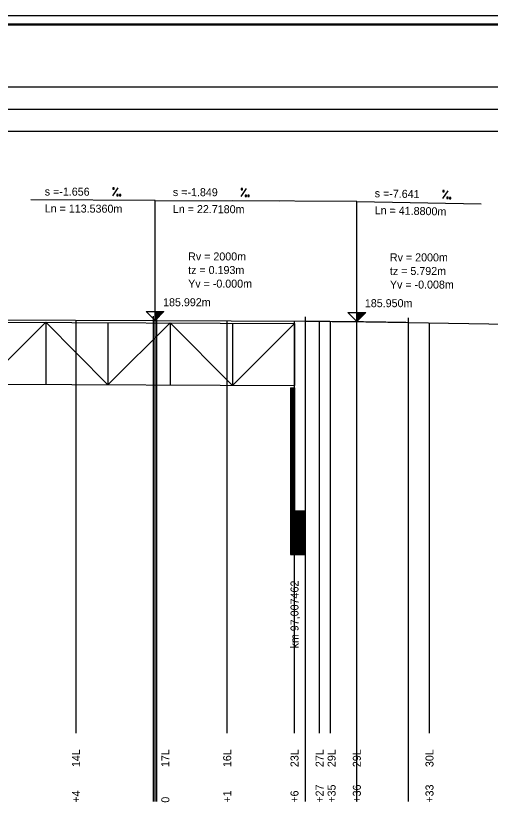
# Model space of a CAD drawing. Extents: x 0 to 10087, y -805 to 297.
# Drawn here: x 1332.1 to 1439, y 120.1 to 297 of the extents above; entities that cross this region are included whole.
import ezdxf

# ---------------------------------------------------------------- set-up
doc = ezdxf.new("R2010")
doc.units = 0
for name, color, linetype in [('CARKY_HODNOT', 7, 'Continuous'), ('NIVELETA_CARA', 7, 'Continuous'), ('NIVELETA_TEXT', 7, 'Continuous'), ('OBJEKTY_TEXT', 7, 'Continuous'), ('OBJEKTY_TVAR', 7, 'Continuous'), ('RAM', 7, 'Continuous'), ('TEXT', 7, 'Continuous')]:
    doc.layers.add(name, color=color, linetype=linetype)

msp = doc.modelspace()

# ---------------------------------------------------------------- linework, layer by layer
at = {"layer": 'CARKY_HODNOT'}
for p, q in [((1345.73, 138.35), (1345.73, 228.53)), ((1363.14, 138.35), (1363.14, 228.46)), ((1363.52, 138.35), (1363.52, 228.46)), ((1363.53, 138.35), (1363.53, 228.46)), ((1363.91, 138.35), (1363.91, 228.46)), ((1379.76, 138.35), (1379.76, 228.38)), ((1394.92, 138.35), (1394.92, 228.31)), ((1397.38, 138.35), (1397.38, 228.3)), ((1400.57, 138.35), (1400.57, 228.29)), ((1403.01, 138.35), (1403.01, 228.27)), ((1408.95, 138.35), (1408.95, 228.21)), ((1408.96, 138.35), (1408.96, 228.21)), ((1420.55, 138.35), (1420.55, 228.03)), ((1425.31, 138.35), (1425.31, 227.94)), ((1345.73, 135.65), (1345.73, 138.35)), ((1363.14, 126.2), (1363.14, 138.35)), ((1363.52, 135.65), (1363.52, 138.35)), ((1363.53, 126.2), (1363.53, 138.35)), ((1363.91, 126.2), (1363.91, 138.35)), ((1379.76, 135.65), (1379.76, 138.35)), ((1394.92, 135.65), (1394.92, 138.35)), ((1397.38, 126.2), (1397.38, 138.35)), ((1400.57, 135.65), (1400.57, 138.35)), ((1403.01, 135.65), (1403.01, 138.35)), ((1408.95, 135.65), (1408.95, 138.35)), ((1408.96, 126.2), (1408.96, 138.35)), ((1420.55, 126.2), (1420.55, 138.35)), ((1425.31, 135.65), (1425.31, 138.35)), ((1363.14, 120.25), (1363.14, 126.2)), ((1363.52, 124.35), (1363.52, 126.2)), ((1363.53, 120.25), (1363.53, 126.2)), ((1363.91, 120.25), (1363.91, 126.2)), ((1397.38, 120.25), (1397.38, 126.2)), ((1408.96, 120.25), (1408.96, 126.2)), ((1420.55, 120.25), (1420.55, 126.2))]:
    msp.add_line(p, q, dxfattribs=at)
at = {"layer": 'NIVELETA_CARA'}
for p, q in [((300, 281), (8321.33, 281)), ((300, 276), (8321.33, 276)), ((300, 271), (8321.33, 271)), ((1363.53, 255.46), (1335.53, 255.58)), ((1363.53, 228.46), (1363.53, 255.46)), ((1363.53, 255.46), (1391.53, 255.33)), ((1408.96, 255.25), (1380.96, 255.38)), ((1408.96, 228.25), (1408.96, 255.25)), ((1408.96, 255.25), (1436.96, 254.72)), ((1363.53, 228.46), (1361.53, 230.46)), ((1361.53, 230.46), (1365.53, 230.46)), ((1363.53, 228.46), (1363.53, 230.46)), ((1365.53, 230.46), (1363.53, 228.46)), ((1363.59, 228.53), (1363.59, 230.46)), ((1363.66, 228.59), (1363.66, 230.46)), ((1363.73, 228.66), (1363.73, 230.46)), ((1363.79, 228.73), (1363.79, 230.46)), ((1363.86, 228.79), (1363.86, 230.46)), ((1363.93, 228.86), (1363.93, 230.46)), ((1363.99, 228.93), (1363.99, 230.46)), ((1364.06, 228.99), (1364.06, 230.46)), ((1364.13, 229.06), (1364.13, 230.46)), ((1364.19, 229.13), (1364.19, 230.46)), ((1364.26, 229.19), (1364.26, 230.46)), ((1364.33, 229.26), (1364.33, 230.46)), ((1364.39, 229.33), (1364.39, 230.46)), ((1364.46, 229.39), (1364.46, 230.46)), ((1364.53, 229.46), (1364.53, 230.46)), ((1364.59, 229.53), (1364.59, 230.46)), ((1364.66, 229.59), (1364.66, 230.46)), ((1364.73, 229.66), (1364.73, 230.46)), ((1364.79, 229.73), (1364.79, 230.46)), ((1364.86, 229.79), (1364.86, 230.46)), ((1364.93, 229.86), (1364.93, 230.46)), ((1364.99, 229.93), (1364.99, 230.46)), ((1365.06, 229.99), (1365.06, 230.46)), ((1365.13, 230.06), (1365.13, 230.46)), ((1365.19, 230.13), (1365.19, 230.46)), ((1365.26, 230.19), (1365.26, 230.46)), ((1365.33, 230.26), (1365.33, 230.46)), ((1365.39, 230.33), (1365.39, 230.46)), ((1365.46, 230.39), (1365.46, 230.46)), ((1408.96, 228.25), (1406.96, 230.25)), ((1406.96, 230.25), (1410.96, 230.25)), ((1408.96, 228.25), (1408.96, 230.25)), ((1410.96, 230.25), (1408.96, 228.25)), ((1409.03, 228.32), (1409.03, 230.25)), ((1409.1, 228.38), (1409.1, 230.25)), ((1409.16, 228.45), (1409.16, 230.25)), ((1409.23, 228.52), (1409.23, 230.25)), ((1409.3, 228.58), (1409.3, 230.25)), ((1409.36, 228.65), (1409.36, 230.25)), ((1409.43, 228.72), (1409.43, 230.25)), ((1409.5, 228.78), (1409.5, 230.25)), ((1409.56, 228.85), (1409.56, 230.25)), ((1409.63, 228.92), (1409.63, 230.25)), ((1409.7, 228.98), (1409.7, 230.25)), ((1409.76, 229.05), (1409.76, 230.25)), ((1409.83, 229.12), (1409.83, 230.25)), ((1409.9, 229.18), (1409.9, 230.25)), ((1409.96, 229.25), (1409.96, 230.25)), ((1410.03, 229.32), (1410.03, 230.25)), ((1410.1, 229.38), (1410.1, 230.25)), ((1410.16, 229.45), (1410.16, 230.25)), ((1410.23, 229.52), (1410.23, 230.25)), ((1410.3, 229.58), (1410.3, 230.25)), ((1410.36, 229.65), (1410.36, 230.25)), ((1410.43, 229.72), (1410.43, 230.25)), ((1410.5, 229.78), (1410.5, 230.25)), ((1410.56, 229.85), (1410.56, 230.25)), ((1410.63, 229.92), (1410.63, 230.25)), ((1410.7, 229.98), (1410.7, 230.25)), ((1410.76, 230.05), (1410.76, 230.25)), ((1410.83, 230.12), (1410.83, 230.25)), ((1410.9, 230.18), (1410.9, 230.25)), ((1153.84, 229.33), (1363.14, 228.46)), ((1363.14, 228.46), (1363.14, 229.46)), ((1363.14, 228.46), (1363.53, 228.46)), ((1363.14, 228.46), (1363.53, 228.46)), ((1363.53, 228.46), (1363.91, 228.46)), ((1363.53, 228.46), (1363.91, 228.46)), ((1363.91, 228.46), (1363.91, 229.46)), ((1363.91, 228.46), (1397.38, 228.3)), ((1397.38, 228.3), (1397.38, 229.3)), ((1397.38, 228.3), (1408.96, 228.25)), ((1397.38, 228.3), (1397.88, 228.3)), ((1397.88, 228.3), (1398.38, 228.3)), ((1398.38, 228.3), (1398.88, 228.3)), ((1398.88, 228.3), (1399.38, 228.29)), ((1399.38, 228.29), (1399.88, 228.29)), ((1399.88, 228.29), (1400.38, 228.29)), ((1400.38, 228.29), (1400.88, 228.28)), ((1400.88, 228.28), (1401.38, 228.28)), ((1401.38, 228.28), (1401.88, 228.28)), ((1401.88, 228.28), (1402.38, 228.27)), ((1402.38, 228.27), (1402.88, 228.27)), ((1402.88, 228.27), (1403.38, 228.26)), ((1403.38, 228.26), (1403.88, 228.26)), ((1403.88, 228.26), (1404.38, 228.26)), ((1404.38, 228.26), (1404.88, 228.25)), ((1404.88, 228.25), (1405.38, 228.25)), ((1405.38, 228.25), (1405.88, 228.24)), ((1405.88, 228.24), (1406.38, 228.24)), ((1406.38, 228.24), (1406.88, 228.23)), ((1406.88, 228.23), (1407.38, 228.23)), ((1407.38, 228.23), (1407.88, 228.22)), ((1407.88, 228.22), (1408.38, 228.21)), ((1408.38, 228.21), (1408.88, 228.21)), ((1408.88, 228.21), (1408.96, 228.21)), ((1408.96, 228.25), (1420.55, 228.03)), ((1420.55, 228.03), (1420.55, 229.03)), ((1408.96, 228.21), (1409.46, 228.2)), ((1409.46, 228.2), (1409.96, 228.2)), ((1409.96, 228.2), (1410.46, 228.19)), ((1410.46, 228.19), (1410.96, 228.18)), ((1410.96, 228.18), (1411.46, 228.18)), ((1411.46, 228.18), (1411.96, 228.17)), ((1411.96, 228.17), (1412.46, 228.16)), ((1412.46, 228.16), (1412.96, 228.16)), ((1412.96, 228.16), (1413.46, 228.15)), ((1413.46, 228.15), (1413.96, 228.14)), ((1413.96, 228.14), (1414.46, 228.13)), ((1414.46, 228.13), (1414.96, 228.13)), ((1414.96, 228.13), (1415.46, 228.12)), ((1415.46, 228.12), (1415.96, 228.11)), ((1415.96, 228.11), (1416.46, 228.1)), ((1416.46, 228.1), (1416.96, 228.09)), ((1416.96, 228.09), (1417.46, 228.08)), ((1417.46, 228.08), (1417.96, 228.08)), ((1417.96, 228.08), (1418.46, 228.07)), ((1418.46, 228.07), (1418.96, 228.06)), ((1418.96, 228.06), (1419.46, 228.05)), ((1419.46, 228.05), (1419.96, 228.04)), ((1419.96, 228.04), (1420.46, 228.03)), ((1420.46, 228.03), (1420.55, 228.03)), ((1420.55, 228.03), (1486.78, 226.76))]:
    msp.add_line(p, q, dxfattribs=at)
at = {"layer": 'NIVELETA_TEXT'}
for p, q in [((1354.04, 258.3), (1354.03, 258)), ((1354.03, 256.5), (1355.22, 258.29)), ((1354.33, 258.29), (1354.04, 258.3)), ((1354.04, 258.3), (1354.04, 258.29)), ((1354.33, 258), (1354.33, 258.29)), ((1354.03, 258), (1354.33, 258)), ((1354.94, 256.8), (1354.94, 256.5)), ((1355.24, 256.79), (1354.94, 256.8)), ((1354.94, 256.8), (1354.94, 256.79)), ((1355.23, 256.5), (1355.24, 256.79)), ((1355.55, 256.79), (1355.55, 256.5)), ((1355.56, 256.79), (1355.55, 256.79)), ((1355.85, 256.79), (1355.56, 256.79)), ((1355.85, 256.49), (1355.85, 256.79)), ((1382.88, 256.37), (1384.08, 258.16)), ((1382.89, 258.17), (1382.89, 257.87)), ((1383.18, 258.17), (1382.89, 258.17)), ((1382.89, 258.17), (1382.89, 258.16)), ((1382.89, 257.87), (1383.18, 257.87)), ((1383.18, 257.87), (1383.18, 258.17)), ((1383.79, 256.67), (1383.79, 256.37)), ((1384.09, 256.66), (1383.79, 256.67)), ((1383.79, 256.67), (1383.79, 256.66)), ((1384.08, 256.37), (1384.09, 256.66)), ((1384.4, 256.66), (1384.4, 256.37)), ((1384.41, 256.66), (1384.4, 256.66)), ((1384.7, 256.66), (1384.41, 256.66)), ((1384.7, 256.36), (1384.7, 256.66)), ((1428.31, 255.88), (1429.53, 257.65)), ((1428.35, 257.68), (1428.34, 257.38)), ((1428.34, 257.38), (1428.64, 257.37)), ((1428.64, 257.67), (1428.35, 257.68)), ((1428.35, 257.68), (1428.35, 257.67)), ((1428.64, 257.37), (1428.64, 257.67)), ((1354.94, 256.5), (1355.23, 256.5)), ((1355.55, 256.5), (1355.85, 256.49)), ((1383.79, 256.37), (1384.08, 256.37)), ((1384.4, 256.37), (1384.7, 256.36)), ((1429.23, 256.16), (1429.22, 255.87)), ((1429.22, 255.87), (1429.52, 255.86)), ((1429.52, 256.16), (1429.23, 256.16)), ((1429.23, 256.16), (1429.23, 256.16)), ((1429.52, 255.86), (1429.52, 256.16)), ((1429.84, 256.15), (1429.83, 255.85)), ((1429.83, 255.85), (1430.13, 255.85)), ((1429.85, 256.15), (1429.84, 256.15)), ((1430.14, 256.15), (1429.85, 256.15)), ((1430.13, 255.85), (1430.14, 256.15))]:
    msp.add_line(p, q, dxfattribs=at)
at = {"layer": 'OBJEKTY_TVAR'}
for p, q in [((1310.89, 228.18), (1394.92, 227.81)), ((1324.9, 214.11), (1338.9, 228.06)), ((1338.9, 228.06), (1338.9, 214.05)), ((1338.9, 228.06), (1352.91, 213.99)), ((1352.91, 228), (1352.91, 213.99)), ((1352.91, 213.99), (1366.91, 227.94)), ((1366.91, 227.94), (1366.91, 213.93)), ((1366.91, 227.94), (1380.92, 213.87)), ((1380.92, 227.88), (1380.92, 213.87)), ((1380.92, 213.87), (1394.92, 227.81)), ((1394.92, 227.81), (1394.92, 213.81)), ((1310.89, 214.17), (1394.92, 213.81)), ((1393.99, 213.31), (1393.99, 185.65)), ((1393.99, 213.31), (1394.92, 213.31)), ((1394.09, 213.31), (1394.09, 185.65)), ((1394.19, 213.31), (1394.19, 185.65)), ((1394.29, 213.31), (1394.29, 185.65)), ((1394.39, 213.31), (1394.39, 185.65)), ((1394.46, 213.31), (1394.46, 185.65)), ((1394.49, 213.31), (1394.49, 185.65)), ((1394.59, 213.31), (1394.59, 185.65)), ((1394.69, 213.31), (1394.69, 185.65)), ((1394.79, 213.31), (1394.79, 185.65)), ((1394.89, 213.31), (1394.89, 185.65)), ((1394.92, 213.31), (1394.92, 185.65)), ((1393.99, 185.65), (1397.27, 185.65)), ((1393.99, 185.65), (1393.99, 175.8)), ((1393.99, 185.55), (1397.27, 185.55)), ((1393.99, 185.45), (1397.27, 185.45)), ((1393.99, 185.35), (1397.27, 185.35)), ((1393.99, 185.25), (1397.27, 185.25)), ((1393.99, 185.15), (1397.27, 185.15)), ((1393.99, 185.05), (1397.27, 185.05)), ((1393.99, 184.95), (1397.27, 184.95)), ((1393.99, 184.85), (1397.27, 184.85)), ((1393.99, 184.75), (1397.27, 184.75)), ((1393.99, 184.65), (1397.27, 184.65)), ((1393.99, 184.55), (1397.27, 184.55)), ((1393.99, 184.45), (1397.27, 184.45)), ((1393.99, 184.35), (1397.27, 184.35)), ((1393.99, 184.25), (1397.27, 184.25)), ((1393.99, 184.15), (1397.27, 184.15)), ((1393.99, 184.05), (1397.27, 184.05)), ((1397.27, 185.65), (1397.27, 175.8)), ((1393.99, 183.95), (1397.27, 183.95)), ((1393.99, 183.85), (1397.27, 183.85)), ((1393.99, 183.75), (1397.27, 183.75)), ((1393.99, 183.65), (1397.27, 183.65)), ((1393.99, 183.55), (1397.27, 183.55)), ((1393.99, 183.45), (1397.27, 183.45)), ((1393.99, 183.35), (1397.27, 183.35)), ((1393.99, 183.25), (1397.27, 183.25)), ((1393.99, 183.15), (1397.27, 183.15)), ((1393.99, 183.05), (1397.27, 183.05)), ((1393.99, 182.95), (1397.27, 182.95)), ((1393.99, 182.85), (1397.27, 182.85)), ((1393.99, 182.75), (1397.27, 182.75)), ((1393.99, 182.65), (1397.27, 182.65)), ((1393.99, 182.55), (1397.27, 182.55)), ((1393.99, 182.45), (1397.27, 182.45)), ((1393.99, 182.35), (1397.27, 182.35)), ((1393.99, 182.25), (1397.27, 182.25)), ((1393.99, 182.15), (1397.27, 182.15)), ((1393.99, 182.05), (1397.27, 182.05)), ((1393.99, 181.95), (1397.27, 181.95)), ((1393.99, 181.85), (1397.27, 181.85)), ((1393.99, 181.75), (1397.27, 181.75)), ((1393.99, 181.65), (1397.27, 181.65)), ((1393.99, 181.55), (1397.27, 181.55)), ((1393.99, 181.45), (1397.27, 181.45)), ((1393.99, 181.35), (1397.27, 181.35)), ((1393.99, 181.25), (1397.27, 181.25)), ((1393.99, 181.15), (1397.27, 181.15)), ((1393.99, 181.05), (1397.27, 181.05)), ((1393.99, 180.95), (1397.27, 180.95)), ((1393.99, 180.85), (1397.27, 180.85)), ((1393.99, 180.75), (1397.27, 180.75)), ((1393.99, 180.65), (1397.27, 180.65)), ((1393.99, 180.55), (1397.27, 180.55)), ((1393.99, 180.45), (1397.27, 180.45)), ((1393.99, 180.35), (1397.27, 180.35)), ((1393.99, 180.25), (1397.27, 180.25)), ((1393.99, 180.15), (1397.27, 180.15)), ((1393.99, 180.05), (1397.27, 180.05)), ((1393.99, 179.95), (1397.27, 179.95)), ((1393.99, 179.85), (1397.27, 179.85)), ((1393.99, 179.75), (1397.27, 179.75)), ((1393.99, 179.65), (1397.27, 179.65)), ((1393.99, 179.55), (1397.27, 179.55)), ((1393.99, 179.45), (1397.27, 179.45)), ((1393.99, 179.35), (1397.27, 179.35)), ((1393.99, 179.25), (1397.27, 179.25)), ((1393.99, 179.15), (1397.27, 179.15)), ((1393.99, 179.05), (1397.27, 179.05)), ((1393.99, 178.95), (1397.27, 178.95)), ((1393.99, 178.85), (1397.27, 178.85)), ((1393.99, 178.75), (1397.27, 178.75)), ((1393.99, 178.65), (1397.27, 178.65)), ((1393.99, 178.55), (1397.27, 178.55)), ((1393.99, 178.45), (1397.27, 178.45)), ((1393.99, 178.35), (1397.27, 178.35)), ((1393.99, 178.25), (1397.27, 178.25)), ((1393.99, 178.15), (1397.27, 178.15)), ((1393.99, 178.05), (1397.27, 178.05)), ((1393.99, 177.95), (1397.27, 177.95)), ((1393.99, 177.85), (1397.27, 177.85)), ((1393.99, 177.75), (1397.27, 177.75)), ((1393.99, 177.65), (1397.27, 177.65)), ((1393.99, 177.55), (1397.27, 177.55)), ((1393.99, 177.45), (1397.27, 177.45)), ((1393.99, 177.35), (1397.27, 177.35)), ((1393.99, 177.25), (1397.27, 177.25)), ((1393.99, 177.15), (1397.27, 177.15)), ((1393.99, 177.05), (1397.27, 177.05)), ((1393.99, 176.95), (1397.27, 176.95)), ((1393.99, 176.85), (1397.27, 176.85)), ((1393.99, 176.75), (1397.27, 176.75)), ((1393.99, 176.65), (1397.27, 176.65)), ((1393.99, 176.55), (1397.27, 176.55)), ((1393.99, 176.45), (1397.27, 176.45)), ((1393.99, 176.35), (1397.27, 176.35)), ((1393.99, 176.25), (1397.27, 176.25)), ((1393.99, 176.15), (1397.27, 176.15)), ((1393.99, 176.05), (1397.27, 176.05)), ((1393.99, 175.95), (1397.27, 175.95)), ((1393.99, 175.85), (1397.27, 175.85)), ((1393.99, 175.8), (1397.27, 175.8))]:
    msp.add_line(p, q, dxfattribs=at)
at = {"layer": 'RAM'}
for p, q in [((8636.33, 297), (0, 297)), ((8634.33, 295.1), (2, 295.1)), ((8634.33, 295), (2, 295)), ((8634.33, 294.9), (2, 294.9))]:
    msp.add_line(p, q, dxfattribs=at)

# ---------------------------------------------------------------- texts
at = {"layer": 'NIVELETA_TEXT'}
for s, rotation, p in [('s =-1.656', 359.7628, (1338.68, 256.56)), ('s =-1.849', 359.7352, (1367.53, 256.44)), ('s =-7.641', 358.9057, (1412.96, 256.17)), ('Ln = 113.5360m', 359.7628, (1338.68, 252.76)), ('Ln = 22.7180m', 359.7352, (1367.53, 252.64)), ('Ln = 41.8800m', 358.9057, (1412.96, 252.37))]:
    msp.add_text(s, height=1.8, rotation=rotation, dxfattribs=at).set_placement(p)
for s, p in [('Rv = 2000m', (1370.97, 241.96)), ('Rv = 2000m', (1416.4, 241.75)), ('tz = 0.193m', (1370.97, 238.9)), ('tz = 5.792m', (1416.4, 238.69)), ('Yv = -0.000m', (1370.97, 235.84)), ('Yv = -0.008m', (1416.4, 235.63)), ('185.992m', (1365.33, 231.66)), ('185.950m', (1410.76, 231.45))]:
    msp.add_text(s, height=1.8, dxfattribs=at).set_placement(p)
at = {"layer": 'OBJEKTY_TEXT'}
msp.add_text('km 97,007462', height=1.8, rotation=90, dxfattribs=at).set_placement((1395.82, 154.69))
at = {"layer": 'TEXT'}
for s, p in [('14L', (1346.63, 128)), ('17L', (1366.74, 128)), ('16L', (1380.66, 128)), ('23L', (1395.82, 128)), ('27L', (1401.47, 128)), ('29L', (1404.17, 128)), ('29L', (1409.85, 128)), ('30L', (1426.21, 128)), ('+27', (1401.47, 120)), ('+35', (1404.17, 120)), ('+36', (1409.85, 120)), ('+33', (1426.21, 120)), ('+4', (1346.63, 120)), ('+1', (1380.66, 120)), ('+6', (1395.82, 120)), ('0', (1366.74, 120))]:
    msp.add_text(s, height=1.8, rotation=90, dxfattribs=at).set_placement(p)

doc.saveas('drawing.dxf')
